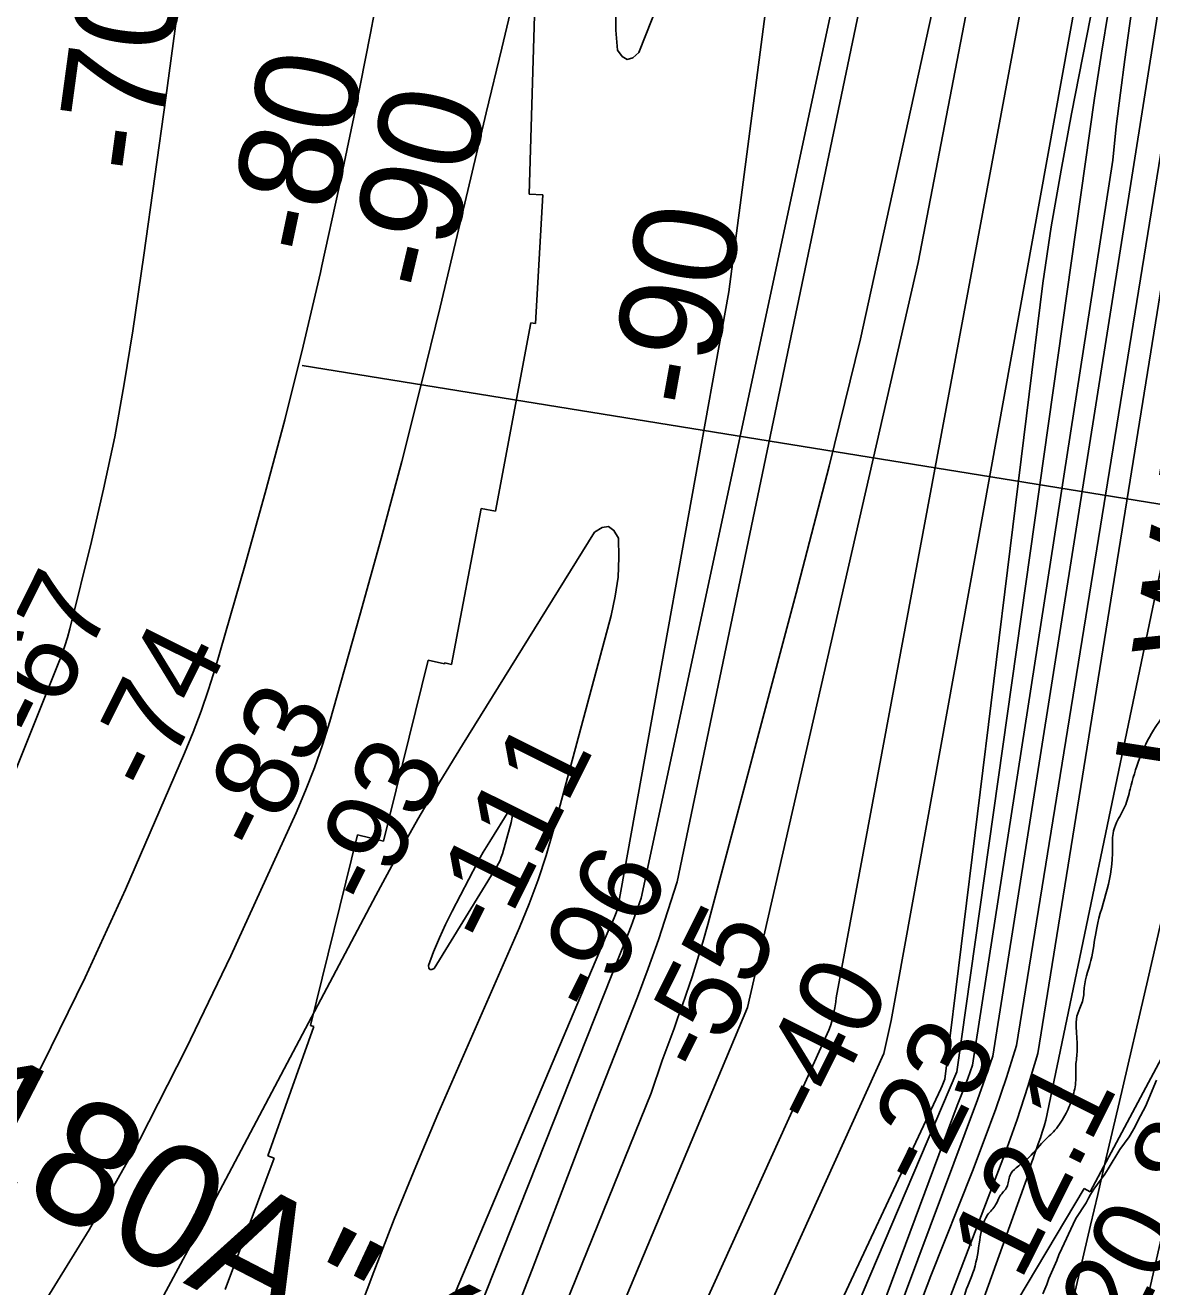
# Model space of a CAD drawing. Extents: x 3361039 to 3398939, y 576572 to 602007.
# Drawn here: x 3386421 to 3387331, y 598351 to 599369 of the extents above; entities that cross this region are included whole.
import ezdxf

# ---------------------------------------------------------------- set-up
doc = ezdxf.new("R2010")
doc.units = 0
for name, color, linetype in [('V-CHAN-NAID', 7, 'Continuous'), ('V-RIVR-EDGE', 7, 'Continuous'), ('V-RIVR-RANG', 7, 'Continuous'), ('V-RRAP-RVMT', 7, 'Continuous'), ('V-SITE-VEGE', 7, 'Continuous'), ('V-TOPO-DPTH', 7, 'Continuous'), ('V-TOPO-MAJR', 7, 'Continuous'), ('V-TOPO-MINR', 7, 'Continuous'), ('V-TOPO-MINR-IDEN', 7, 'Continuous'), ('V-TOPO-WATR', 7, 'Continuous'), ('V-TOPO-WATR-IDEN', 7, 'Continuous')]:
    doc.layers.add(name, color=color, linetype=linetype)

msp = doc.modelspace()

# ---------------------------------------------------------------- linework, layer by layer
at = {"layer": 'V-RIVR-EDGE'}
msp.add_spline([(3387035.8, 597712.7), (3387047.5, 597738.8), (3387054.9, 597753.2), (3387058.1, 597763.8), (3387063.4, 597770.8), (3387068.4, 597779.3), (3387074.8, 597795.8), (3387086.1, 597818.7), (3387092.8, 597830.6), (3387093.9, 597835.6), (3387097.8, 597846.5), (3387103.1, 597854.2), (3387105.2, 597864.4), (3387109.9, 597882.4), (3387115.2, 597909.9), (3387117.4, 597927.8), (3387121.3, 597963.8), (3387121.1, 597990.5), (3387122.2, 598030), (3387122.3, 598056.8), (3387121.7, 598086.7), (3387121.7, 598099.4), (3387124.5, 598116.7), (3387130.2, 598141), (3387137.4, 598168.5), (3387146.6, 598188.5), (3387150.5, 598200.5), (3387153.7, 598215.6), (3387157.3, 598236.1), (3387156.6, 598249.5), (3387159.1, 598262.8), (3387165.5, 598291.7), (3387167.6, 598300.2), (3387174.4, 598323.1), (3387179.4, 598343.5), (3387187.2, 598364.6), (3387191.8, 598388.2), (3387198.2, 598408.6), (3387204.6, 598416.7), (3387208.1, 598423.8), (3387213.8, 598431.1), (3387216.3, 598440.6), (3387221.2, 598446.6), (3387229.7, 598453.3), (3387243.5, 598468.1), (3387252.3, 598476.9), (3387261.5, 598490.6), (3387266.8, 598504), (3387269.3, 598517), (3387269.3, 598527.6), (3387270.4, 598539.9), (3387269.8, 598556.8), (3387269.8, 598566.7), (3387272.6, 598575.5), (3387274.7, 598580.8), (3387276.2, 598592), (3387282.2, 598617), (3387286.2, 598640.3), (3387294.7, 598671.6), (3387299, 598704), (3387299.4, 598716.4), (3387302.2, 598725.2), (3387309, 598738.2), (3387313.2, 598752.3), (3387332, 598799.8), (3387344.7, 598817.4), (3387353.6, 598828.3), (3387361.4, 598838.8), (3387376.9, 598868.4), (3387385.1, 598885.3), (3387395.3, 598901.5), (3387408.1, 598925), (3387425.4, 598953.5), (3387435, 598969.7), (3387436.1, 598977.1), (3387437.1, 598988.8), (3387433, 599029.3), (3387428.8, 599052.6), (3387427.5, 599065.9), (3387425.7, 599080.4), (3387425.8, 599092), (3387427.7, 599161.8), (3387425.7, 599208), (3387426.2, 599247.4), (3387428, 599280.5), (3387431.6, 599320.7), (3387432.4, 599340.8), (3387428.9, 599359.8), (3387429.3, 599371.8), (3387429.3, 599383.4), (3387432.2, 599392.9), (3387435.7, 599396.8), (3387443.8, 599402.1), (3387448.8, 599408), (3387453.7, 599419.7), (3387455.1, 599430.9), (3387455.2, 599438.7), (3387455.9, 599451), (3387454.5, 599465.5), (3387450.7, 599482), (3387440.5, 599502.9), (3387424.7, 599530.7), (3387411.8, 599557.9), (3387402.7, 599578), (3387395.7, 599601.6), (3387394.3, 599611.9), (3387394.7, 599629.1), (3387395.1, 599640.8), (3387393, 599657), (3387390.5, 599667.5), (3387386, 599691.9), (3387381.5, 599710.9), (3387378, 599719.7), (3387375.2, 599722.9), (3387371, 599725.4), (3387370.6, 599734.2), (3387372.8, 599758.5), (3387377.5, 599788.4), (3387381.4, 599808.5), (3387385, 599830.4), (3387389.6, 599840.9), (3387397, 599842.3), (3387399.8, 599846.5), (3387396.3, 599856.4), (3387392.8, 599867), (3387392.1, 599875.4), (3387391.8, 599896.6), (3387391.9, 599913.8), (3387391.2, 599920.2), (3387390.8, 599926.9), (3387390.9, 599936.4), (3387393, 599959), (3387396.2, 599978.3), (3387394.5, 599984), (3387394.5, 599992.4), (3387396, 600010.4), (3387397.8, 600031.2), (3387400, 600061.8), (3387403.2, 600096), (3387404.4, 600126.7), (3387408.3, 600169.3), (3387410.2, 600200.6), (3387410.3, 600202)], degree=3, dxfattribs=at)
at = {"layer": 'V-RIVR-RANG'}
msp.add_line((3387829.5, 598902.8), (3386644.9, 599094.2), dxfattribs=at)
at = {"layer": 'V-RRAP-RVMT'}
for p, q in [((3386828.1, 599232.5), (3386832.6, 599376.7)), ((3386839.3, 599231.9), (3386828.1, 599232.5)), ((3386833.2, 599128), (3386839.3, 599231.9)), ((3386801.1, 598976.7), (3386829.5, 599128.7)), ((3386829.5, 599128.7), (3386833.2, 599128)), ((3386765.6, 598852.9), (3386789.5, 598978.7)), ((3386789.5, 598978.7), (3386801.1, 598976.7)), ((3386710.6, 598710.3), (3386746.7, 598856.2)), ((3386746.7, 598856.2), (3386759.8, 598853.4)), ((3386759.8, 598853.4), (3386760, 598854.2)), ((3386760, 598854.2), (3386765.6, 598852.9)), ((3386651.6, 598561.5), (3386689.6, 598715.4)), ((3386689.6, 598715.4), (3386710.6, 598710.3)), ((3386617.2, 598456.2), (3386654.5, 598560.6)), ((3386654.5, 598560.6), (3386651.6, 598561.5)), ((3387344.9, 598547.3), (3387281, 598427.2)), ((3386582.9, 598348.4), (3386622.4, 598454.3)), ((3386622.4, 598454.3), (3386617.2, 598456.2)), ((3387276.1, 598429.9), (3387208.2, 598316)), ((3387281, 598427.2), (3387276.1, 598429.9))]:
    msp.add_line(p, q, dxfattribs=at)
at = {"layer": 'V-SITE-VEGE'}
for p, q in [((3387325.7, 598496.2), (3387334.5, 598517.3)), ((3387319.8, 598485), (3387325.7, 598496.2)), ((3387317, 598479.3), (3387319.8, 598485)), ((3387312.3, 598471.5), (3387317, 598479.3)), ((3387304.8, 598461.3), (3387312.3, 598471.5)), ((3387295.5, 598445.7), (3387304.8, 598461.3)), ((3387283.9, 598429.3), (3387292.7, 598441.5)), ((3387292.7, 598441.5), (3387295.5, 598445.7)), ((3387277.7, 598418.3), (3387279.5, 598422)), ((3387279.5, 598422), (3387281.3, 598425.1)), ((3387281.3, 598425.1), (3387283.9, 598429.3)), ((3387269.4, 598405.6), (3387277.7, 598418.3)), ((3387258, 598381.6), (3387267.1, 598401.2)), ((3387267.1, 598401.2), (3387269.4, 598405.6)), ((3387255.7, 598376.4), (3387258, 598381.6)), ((3387247.7, 598357.2), (3387253.9, 598371.7)), ((3387253.9, 598371.7), (3387255.7, 598376.4)), ((3387242.8, 598344.9), (3387245.9, 598352.5)), ((3387245.9, 598352.5), (3387247.7, 598357.2))]:
    msp.add_line(p, q, dxfattribs=at)
at = {"layer": 'V-TOPO-DPTH'}
for points in [[(3387238.5, 600201.5), (3387253.4, 599637.2), (3387254.4, 599613.1), (3387254.5, 599589), (3387253, 599565), (3387250.6, 599541), (3387245.2, 599501.4), (3387238.6, 599457.7), (3387231, 599414.3), (3387075.9, 598583.9), (3387075.6, 598580.6), (3387075.1, 598577.4), (3387074.8, 598575.8), (3387072.4, 598564.7), (3387071.4, 598561.1), (3387070.1, 598557.6), (3386627.9, 597581.8), (3386626.9, 597579.7), (3386624.6, 597575.6), (3386216.2, 597034.3)], [(3386216.2, 597034.3), (3386624.6, 597575.6), (3386626.9, 597579.7), (3386627.9, 597581.8), (3387070.1, 598557.6), (3387071.4, 598561.1), (3387072.4, 598564.7), (3387074.8, 598575.8), (3387075.1, 598577.4), (3387075.6, 598580.6), (3387075.9, 598583.9), (3387231, 599414.3), (3387238.6, 599457.7), (3387245.2, 599501.4), (3387250.6, 599541), (3387253, 599565), (3387254.5, 599589), (3387254.4, 599613.1), (3387253.4, 599637.2), (3387238.5, 600201.5)], [(3386278, 596974), (3386708.9, 597490.1), (3386714, 597497.1), (3386718.8, 597504.3), (3386723.1, 597511.7), (3386727.2, 597519.3), (3386854.3, 597830.5), (3386888.1, 597914.9), (3386923.1, 597998.9), (3386959.8, 598082), (3387160.3, 598510.3), (3387161.5, 598512.8), (3387162.6, 598515.4), (3387163.6, 598518.1), (3387242.6, 599160.5), (3387249.5, 599206.2), (3387257.4, 599251.8), (3387265.9, 599297.2), (3387317.8, 599561.6), (3387318.8, 599568.1), (3387319.5, 599574.7), (3387319.8, 599581.3), (3387319.7, 599587.9), (3387326.8, 600201.7)], [(3387424, 600202), (3387386.3, 599586.4), (3387384.4, 599577.9), (3387382.9, 599569.4), (3387381.6, 599560.8), (3387380.2, 599552.2), (3387379, 599543.6), (3387372, 599495.3), (3387370.6, 599485.6), (3387369.3, 599476), (3387368.1, 599466.3), (3387367, 599456.6), (3387366.2, 599446.9), (3387365.7, 599437.2), (3387221.5, 598545.2), (3387213.3, 598519.6), (3387204.7, 598494.2), (3387195.5, 598469), (3387185.9, 598444), (3387152.3, 598359.3), (3386803, 597438), (3386795.9, 597427.9), (3386788.5, 597418.1), (3386440.2, 596998.2)], [(3386440.2, 596998.2), (3386788.5, 597418.1), (3386795.9, 597427.9), (3386803, 597438), (3387152.3, 598359.3), (3387185.9, 598444), (3387195.5, 598469), (3387204.7, 598494.2), (3387213.3, 598519.6), (3387221.5, 598545.2), (3387365.7, 599437.2), (3387366.2, 599446.9), (3387367, 599456.6), (3387368.1, 599466.3), (3387369.3, 599476), (3387370.6, 599485.6), (3387372, 599495.3), (3387379, 599543.6), (3387380.2, 599552.2), (3387381.6, 599560.8), (3387382.9, 599569.4), (3387384.4, 599577.9), (3387386.3, 599586.4), (3387424, 600202)], [(3386278, 596974), (3386708.9, 597490.1), (3386714, 597497.1), (3386718.8, 597504.3), (3386723.1, 597511.7), (3386727.2, 597519.3), (3386854.3, 597830.5), (3386888.1, 597914.9), (3386923.1, 597998.9), (3386959.8, 598082), (3387160.3, 598510.3), (3387161.5, 598512.8), (3387162.6, 598515.4), (3387163.6, 598518.1), (3387242.6, 599160.5), (3387249.5, 599206.2), (3387257.4, 599251.8), (3387265.9, 599297.2), (3387317.8, 599561.6)], [(3387298.5, 599549.4), (3387125.2, 598592.2), (3387120.3, 598565.4), (3387114.5, 598538.9), (3386752.7, 597739.9), (3386721.9, 597676.8), (3386678.1, 597588), (3386668.6, 597569.6), (3386658.5, 597551.6), (3386647.7, 597534), (3386636.3, 597516.7), (3386517.2, 597344.8), (3386327.4, 597098.1)], [(3386327.4, 597098.1), (3386517.2, 597344.8), (3386636.3, 597516.7), (3386647.7, 597534), (3386658.5, 597551.6), (3386668.6, 597569.6), (3386678.1, 597588), (3386721.9, 597676.8), (3386752.7, 597739.9), (3387114.5, 598538.9), (3387120.3, 598565.4), (3387125.2, 598592.2), (3387298.5, 599549.4)], [(3387461.7, 599523.6), (3387245.2, 598485), (3387243.8, 598480.2), (3387242.3, 598475.5), (3387240.8, 598470.8), (3387239.1, 598466.1), (3387237.6, 598461.8), (3387236.6, 598459.3), (3387235.7, 598456.7), (3387234.8, 598454.1), (3387233.8, 598451.5), (3387233, 598448.9), (3387232.2, 598446.3), (3387231.5, 598443.7), (3387230.9, 598441), (3386872.5, 597444.1)], [(3387316.4, 599395.3), (3387312.6, 599368.2), (3387308.9, 599341.2), (3387305.4, 599314.1), (3387302, 599287), (3387299.3, 599259.9), (3387186, 598529.5), (3387182.1, 598518.6), (3387178, 598507.7), (3387173.7, 598496.9), (3386787.7, 597458.9), (3386787.5, 597458.4), (3386787.4, 597457.9), (3386786.8, 597456.3), (3386784.7, 597452.4), (3386782.9, 597450.1), (3386780, 597446.7), (3386779.1, 597445.6), (3386299.6, 596912.3)], [(3386299.6, 596912.3), (3386779.1, 597445.6), (3386780, 597446.7), (3386782.9, 597450.1), (3386784.7, 597452.4), (3386786.8, 597456.3), (3386787.4, 597457.9), (3386787.5, 597458.4), (3386787.7, 597458.9), (3387173.7, 598496.9), (3387178, 598507.7), (3387182.1, 598518.6), (3387186, 598529.5), (3387299.3, 599259.9), (3387302, 599287), (3387305.4, 599314.1), (3387308.9, 599341.2), (3387312.6, 599368.2), (3387316.4, 599395.3)]]:
    msp.add_lwpolyline(points, dxfattribs=at)
at = {"layer": 'V-TOPO-MAJR'}
for points in [[(3386195, 597057.3), (3386492.8, 597449.5), (3386526.5, 597500.6), (3386562.5, 597557.1), (3386577.1, 597580.7), (3386591.2, 597604.6), (3386604.7, 597628.9), (3386617.6, 597653.4), (3387004.5, 598575.9), (3387142, 599177.3), (3387220.4, 599583.8), (3387221.3, 599590.2), (3387221.8, 599596.7), (3387221.7, 599603.2), (3387221.3, 599609.8), (3387195.6, 600201.4)], [(3386898.1, 599380.7), (3386898.1, 599364.7), (3386899.5, 599348.6), (3386903.3, 599343.6), (3386907.3, 599341.2), (3386911.8, 599342.6), (3386916.6, 599346.7), (3387025.2, 599620.9)], [(3386686.7, 598319.8), (3386702.7, 598362.7), (3386719.3, 598405.3), (3386736.7, 598447.6), (3386754.6, 598489.8), (3386820.4, 598640.7), (3386828.2, 598659.8), (3386835.5, 598679.1), (3386841.8, 598698.6), (3386847.6, 598718.4), (3386894.4, 598892.4), (3386897.7, 598907.9), (3386900, 598923.4), (3386900.6, 598939.1), (3386900.2, 598954.9), (3386896.6, 598961), (3386892.3, 598964.2), (3386887, 598963.3), (3386881, 598959.6), (3386774.3, 598788.1), (3386756.1, 598758.1), (3386738.3, 598727.9), (3386721.2, 598697.3), (3386704.4, 598666.4), (3386568.7, 598409.6), (3386519.3, 598317.8)]]:
    msp.add_lwpolyline(points, dxfattribs=at)
at = {"layer": 'V-TOPO-MINR'}
for points in [[(3386172.6, 597212.1), (3386216.4, 597271.7), (3386259, 597332.1), (3386300, 597393.7), (3386339.9, 597456), (3386474.9, 597673.5), (3386479.6, 597681.3), (3386484.1, 597689.2), (3386488.4, 597697.2), (3386492.5, 597705.3), (3386525.1, 597771.4), (3386531.5, 597785.2), (3386893.4, 598640.8), (3386895.1, 598644.6), (3386896.8, 598648.5), (3386898.3, 598652.5), (3386899.8, 598656.5), (3386989.3, 599153.5), (3387049.3, 599612.9), (3387051.3, 599633.2), (3387051.1, 599653.7), (3387049.5, 599674.2), (3387001, 600200.8)], [(3386188.3, 597110.8), (3386522.3, 597600.2), (3386526.4, 597606.2), (3386530.5, 597612.2), (3386534.6, 597618.2), (3386538.6, 597624.2), (3386546, 597635), (3386546.4, 597635.6), (3386547.9, 597638.1), (3386548.8, 597640.1), (3386830.6, 598364.6), (3386879.1, 598491.6), (3386915.5, 598584.4), (3386924.2, 598607.4), (3386932.5, 598630.6), (3386940.2, 598653.9), (3386947.6, 598677.3), (3387137.6, 599587.3), (3387138.3, 599601.4), (3387138.6, 599615.4), (3387138.2, 599629.5), (3387137.3, 599643.5), (3387082, 600201.1)], [(3387238.5, 600201.5), (3387253.4, 599637.2), (3387254.4, 599613.1), (3387254.5, 599589), (3387253, 599565), (3387250.6, 599541), (3387245.2, 599501.4), (3387238.6, 599457.7), (3387231, 599414.3), (3387075.9, 598583.9), (3387075.6, 598580.6), (3387075.1, 598577.4), (3387074.8, 598575.8), (3387072.4, 598564.7), (3387071.4, 598561.1), (3387070.1, 598557.6), (3386627.9, 597581.8), (3386626.9, 597579.7), (3386624.6, 597575.6), (3386216.2, 597034.3)], [(3386278, 596974), (3386708.9, 597490.1), (3386714, 597497.1), (3386718.8, 597504.3), (3386723.1, 597511.7), (3386727.2, 597519.3), (3386854.3, 597830.5), (3386888.1, 597914.9), (3386923.1, 597998.9), (3386959.8, 598082), (3387160.3, 598510.3), (3387161.5, 598512.8), (3387162.6, 598515.4), (3387163.6, 598518.1), (3387242.6, 599160.5), (3387249.5, 599206.2), (3387257.4, 599251.8), (3387265.9, 599297.2), (3387317.8, 599561.6), (3387318.8, 599568.1), (3387319.5, 599574.7), (3387319.8, 599581.3), (3387319.7, 599587.9), (3387326.8, 600201.7)], [(3386301.9, 596942.3), (3386711.7, 597466.8), (3386721.7, 597480.4), (3386731.1, 597494.5), (3386739.6, 597509), (3386747.6, 597523.9), (3387173.4, 598524.2), (3387284.4, 599309.9), (3387290.1, 599346.1), (3387323.9, 599553), (3387325.4, 599563), (3387326.6, 599573.1), (3387327.4, 599583.2), (3387327.9, 599593.4), (3387330.7, 599677.7), (3387361.7, 600201.8)], [(3386342, 596929.3), (3386693.6, 597318.5), (3386727.5, 597360.4), (3386786.5, 597435.1), (3386790.2, 597440.1), (3386793.8, 597445.2), (3386797.2, 597450.4), (3387190.1, 598501.6), (3387196.3, 598519), (3387202.3, 598536.6), (3387334.6, 599372.1), (3387336.8, 599390.4), (3387339.1, 599408.6), (3387341.6, 599426.8), (3387344.1, 599444.9), (3387356.6, 599531.3), (3387359.1, 599548.3), (3387361.4, 599565.3), (3387363.7, 599582.3), (3387365.9, 599599.3), (3387368.8, 599616.2), (3387403.7, 600201.9)], [(3386424.4, 596940.2), (3386790.5, 597401.1), (3386801.5, 597415.8), (3386812.1, 597430.7), (3386822, 597446.1), (3386831.3, 597461.9), (3387212.6, 598459.2), (3387221.9, 598485.6), (3387230.5, 598512.2), (3387238.6, 598539), (3387399.1, 599534.7), (3387399, 599536.1), (3387399, 599539), (3387399.5, 599543.4), (3387399.9, 599546.3), (3387401, 599553.9), (3387401.2, 599555.1), (3387401.9, 599558.7), (3387442.7, 600202.1)], [(3386143.8, 597124.5), (3386335.9, 597390), (3386367.4, 597434.8), (3386398.1, 597480.2), (3386427.5, 597526.3), (3386456, 597573.1), (3386484.9, 597621.8), (3386498, 597644.8), (3386510.6, 597668), (3386522.5, 597691.7), (3386533.8, 597715.6), (3386604.5, 597870.9), (3386901.5, 598619.3), (3386906.1, 598630.5), (3386910.5, 598641.7), (3386914.6, 598653), (3386918.6, 598664.3), (3387120.9, 599608.5)], [(3386327.4, 597098.1), (3386517.2, 597344.8), (3386636.3, 597516.7), (3386647.7, 597534), (3386658.5, 597551.6), (3386668.6, 597569.6), (3386678.1, 597588), (3386721.9, 597676.8), (3386752.7, 597739.9), (3387114.5, 598538.9), (3387120.3, 598565.4), (3387125.2, 598592.2), (3387298.5, 599549.4)], [(3386872.5, 597444.1), (3387230.9, 598441), (3387231.5, 598443.7), (3387232.2, 598446.3), (3387233, 598448.9), (3387233.8, 598451.5), (3387234.8, 598454.1), (3387235.7, 598456.7), (3387236.6, 598459.3), (3387237.6, 598461.8), (3387239.1, 598466.1), (3387240.8, 598470.8), (3387242.3, 598475.5), (3387243.8, 598480.2), (3387245.2, 598485), (3387461.7, 599523.6)], [(3386382.3, 597344.6), (3386554.1, 597605.6), (3386560.1, 597615.1), (3386566, 597624.6), (3386571.7, 597634.4), (3386577.2, 597644.2), (3386926.7, 598506.9), (3386929.6, 598515.7), (3386932.5, 598524.4), (3386935.6, 598533.1), (3386938.8, 598541.8), (3386942, 598550.5), (3386945.1, 598559.1), (3386948.2, 598567.8), (3386951.3, 598576.5), (3386954.9, 598586.8), (3386959.6, 598600.8), (3386964.1, 598614.7), (3386968.3, 598628.8), (3386972.3, 598643), (3387043.7, 598910.3), (3387070.3, 599012.9), (3387095.7, 599115.7), (3387183.1, 599514.8)], [(3387267, 598339), (3387281.2, 598400.3), (3387287.1, 598425.2), (3387292.9, 598450.2), (3387298.7, 598475.2), (3387304.5, 598500.1), (3387327.4, 598598.7), (3387341, 598657.3), (3387465.3, 599212.1), (3387477.9, 599277.9), (3387490, 599343.9), (3387518, 599501.5)], [(3386711.9, 599425.1), (3386700.1, 599362.3), (3386687.7, 599299.6), (3386674.6, 599237.1), (3386660.9, 599174.6), (3386659.7, 599169.2), (3386645.7, 599109.7), (3386630.9, 599050.3), (3386615.2, 598991.3), (3386598.7, 598932.4), (3386574.9, 598850.3), (3386569.4, 598832.7), (3386563.5, 598815.3), (3386557, 598798.2), (3386550, 598781.2), (3386502.3, 598671.3), (3386469.8, 598600.2), (3386435.4, 598530.1), (3386398.2, 598461.4)], [(3386818.6, 599402.5), (3386806, 599350.2), (3386793.5, 599298), (3386781.1, 599245.7), (3386768.7, 599193.4), (3386756.3, 599141.3), (3386741.1, 599078.9), (3386725.4, 599016.6), (3386708.8, 598954.5), (3386691.6, 598892.6), (3386667.2, 598806.9), (3386661.4, 598788.1), (3386655, 598769.5), (3386647.8, 598751.2), (3386640, 598733.1), (3386587.3, 598617.7), (3386551.4, 598542.8), (3386513.6, 598469), (3386473, 598396.6), (3386200.7, 597955.6)], [(3386299.6, 596912.3), (3386779.1, 597445.6), (3386780, 597446.7), (3386782.9, 597450.1), (3386784.7, 597452.4), (3386786.8, 597456.3), (3386787.4, 597457.9), (3386787.5, 597458.4), (3386787.7, 597458.9), (3387173.7, 598496.9), (3387178, 598507.7), (3387182.1, 598518.6), (3387186, 598529.5), (3387299.3, 599259.9), (3387302, 599287), (3387305.4, 599314.1), (3387308.9, 599341.2), (3387312.6, 599368.2), (3387316.4, 599395.3)], [(3386543.6, 599374), (3386535, 599310.3), (3386526.1, 599246.7), (3386517.1, 599183.1), (3386508.3, 599122.2), (3386501.4, 599079.4), (3386493.7, 599036.7), (3386484.7, 598994.3), (3386474.9, 598952.1), (3386457.4, 598881.6), (3386455.5, 598874.7), (3386453.5, 598868), (3386451.2, 598861.3), (3386448.7, 598854.7), (3386384.2, 598694.7)], [(3387299.5, 598219.6), (3387343.7, 598413), (3387344.9, 598418.3), (3387346, 598423.6), (3387347, 598428.9), (3387347.9, 598434.2), (3387349.6, 598444.8), (3387351.5, 598455.4), (3387353.7, 598465.9), (3387356.2, 598476.4), (3387358.9, 598486.8), (3387361.8, 598497.3), (3387366.1, 598513), (3387370.3, 598528.7), (3387374.4, 598544.4), (3387378.3, 598560.1), (3387529.4, 599313.7), (3387532.9, 599334.9), (3387536.6, 599356), (3387540.3, 599377.2)], [(3386755.7, 598632.1), (3386751.1, 598621), (3386746.8, 598609.8), (3386747.3, 598607.8), (3386748.1, 598606.6), (3386749.5, 598606.7), (3386751.4, 598607.6), (3386802.1, 598689.7), (3386803.5, 598692.1), (3386804.7, 598694.7), (3386805.7, 598697.3), (3386806.6, 598700), (3386813.6, 598725.2), (3386814.4, 598729.6), (3386814.5, 598731.9), (3386814.4, 598734.1), (3386813.9, 598735), (3386813.3, 598735.5), (3386812.5, 598735.3), (3386811.7, 598734.8), (3386796.3, 598710.1), (3386793.7, 598705.8), (3386791.1, 598701.5), (3386788.7, 598697.1), (3386786.3, 598692.6), (3386766, 598653.7), (3386760.7, 598642.9), (3386755.7, 598632.1)]]:
    msp.add_lwpolyline(points, dxfattribs=at)
at = {"layer": 'V-TOPO-WATR'}
msp.add_lwpolyline([(3386440.2, 596998.2), (3386788.5, 597418.1), (3386795.9, 597427.9), (3386803, 597438), (3387152.3, 598359.3), (3387185.9, 598444), (3387195.5, 598469), (3387204.7, 598494.2), (3387213.3, 598519.6), (3387221.5, 598545.2), (3387365.7, 599437.2), (3387366.2, 599446.9), (3387367, 599456.6), (3387368.1, 599466.3), (3387369.3, 599476), (3387370.6, 599485.6), (3387372, 599495.3), (3387379, 599543.6), (3387380.2, 599552.2), (3387381.6, 599560.8), (3387382.9, 599569.4), (3387384.4, 599577.9), (3387386.3, 599586.4), (3387424, 600202)], dxfattribs=at)

# ---------------------------------------------------------------- texts
at = {"layer": 'V-CHAN-NAID'}
msp.add_text('GEM "180A" (180.9)', height=100, rotation=332.615, dxfattribs=at).set_placement((3386004.6, 598635.6))
at = {"layer": 'V-RIVR-RANG'}
for s, rotation, p in [('-67', 63.5378, (3386436.3, 598788.8)), ('-74', 63.5378, (3386526.7, 598746.1)), ('-83', 63.5378, (3386614.4, 598697.8)), ('-93', 63.5378, (3386704.3, 598653.9)), ('-111', 63.5378, (3386800.6, 598623.1)), ('-96', 63.5378, (3386884.5, 598567.2)), ('-55', 63.5378, (3386972.3, 598519.1)), ('-40', 63.5378, (3387063, 598476.9)), ('-23', 63.5378, (3387149.9, 598427.2)), ('12.1', 63.2583, (3387224.6, 598354.2)), ('20.8', 63.2583, (3387313, 598307.3))]:
    msp.add_text(s, height=67, rotation=rotation, dxfattribs=at).set_placement(p)
at = {"layer": 'V-TOPO-MINR-IDEN'}
for s, rotation, p in [('-70', 82.2847, (3386526.4, 599247)), ('-80', 78.1289, (3386662.6, 599180.1)), ('-90', 76.6022, (3386758.3, 599150.3)), ('-90', 79.7919, (3386971.9, 599057))]:
    msp.add_text(s, height=83, rotation=rotation, dxfattribs=at).set_placement(p)
at = {"layer": 'V-TOPO-WATR-IDEN'}
msp.add_text('L.W.R.P.', height=83, rotation=81.2371, dxfattribs=at).set_placement((3387382.3, 598758.7))

doc.saveas('drawing.dxf')
